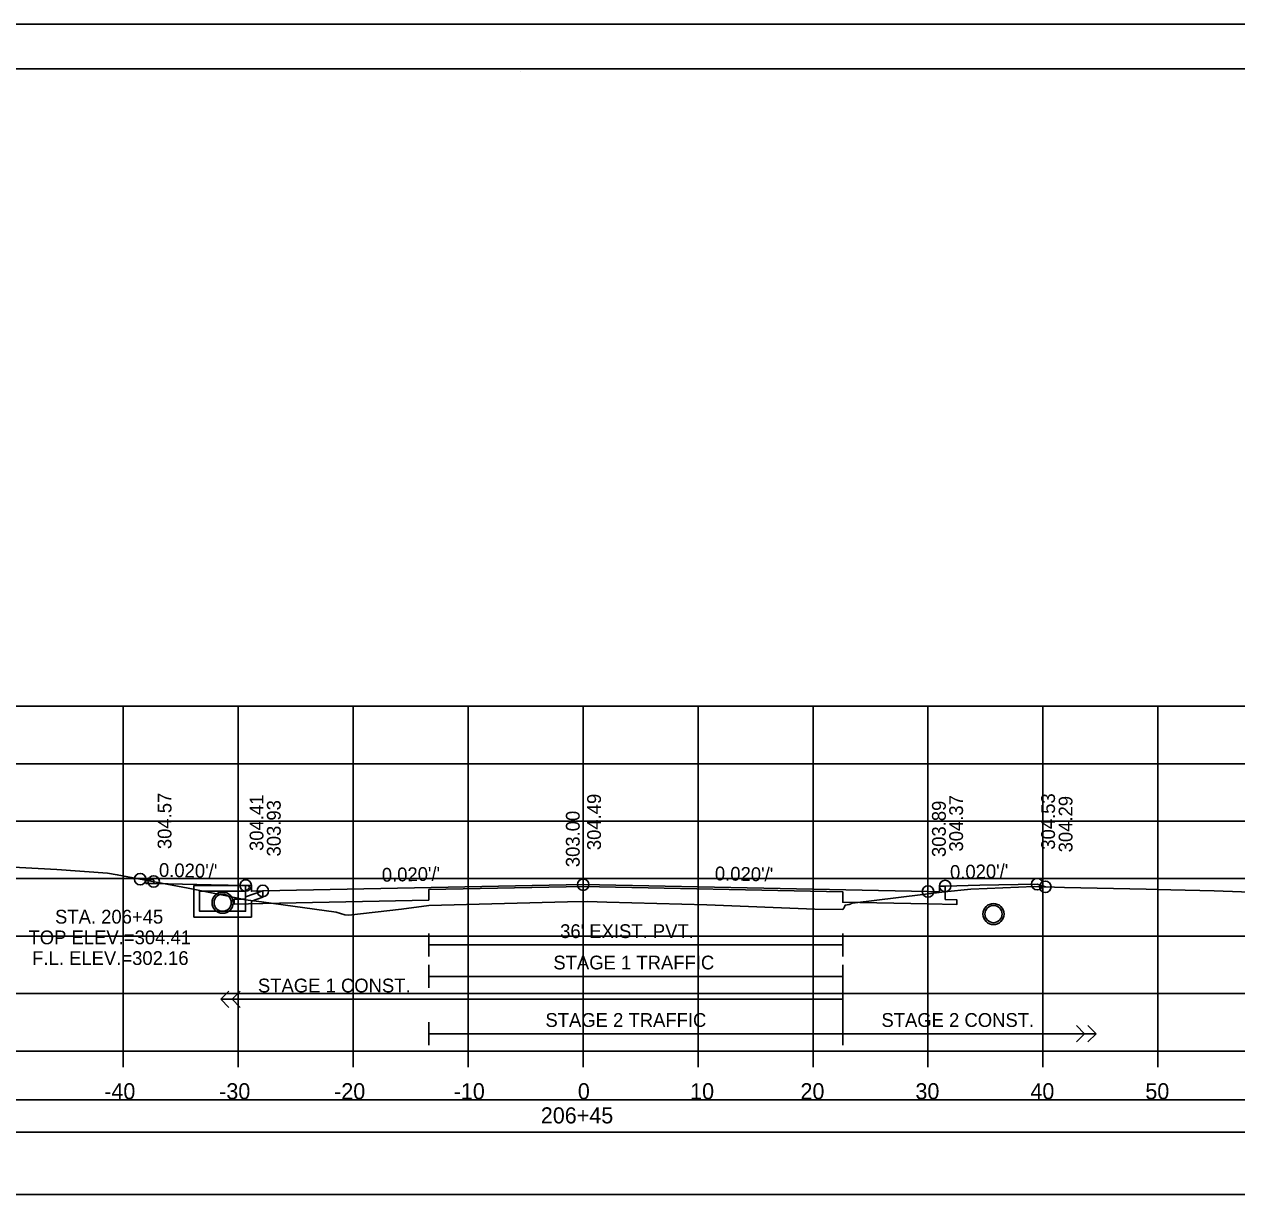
# Model space of a CAD drawing. Extents: x 1368122 to 1710785, y 373130 to 557566.
# Drawn here: x 1369973.6 to 1370079.1, y 374307.6 to 374410.4 of the extents above; entities that cross this region are included whole.
import ezdxf

# ---------------------------------------------------------------- set-up
doc = ezdxf.new("R2010")
doc.units = 0
for name, color, linetype in [('Default', 7, 'Continuous'), ('R_Alt Surface', 7, 'Continuous'), ('R_Axis', 7, 'Continuous'), ('R_Axis Annot', 7, 'Continuous'), ('R_Border', 7, 'Continuous'), ('R_Exist Surface', 7, 'Continuous'), ('R_Fin Surface', 7, 'Continuous'), ('R_Grid', 7, 'Continuous'), ('R_No Plot', 7, 'Continuous'), ('R_Striping', 7, 'Continuous'), ('R_Water', 7, 'Continuous'), ('R_Water Annot', 7, 'Continuous'), ('R_Xsect Elev', 7, 'Continuous'), ('R_Xsect Slope', 7, 'Continuous')]:
    doc.layers.add(name, color=color, linetype=linetype)

msp = doc.modelspace()

# ---------------------------------------------------------------- linework, layer by layer
for points in [[(1369873.09, 374313.94), (1370171.39, 374313.94), (1370171.39, 374316.75), (1369873.09, 374316.75)], [(1369873.09, 374308.52), (1370171.39, 374308.52), (1370171.39, 374313.94), (1369873.09, 374313.94)]]:
    msp.add_lwpolyline(points, close=True)
at = {"layer": 'Default'}
for p, q in [((1369984.27, 374335.92), (1369984.21, 374335.86)), ((1369984.81, 374335.94), (1369984.27, 374335.94)), ((1369984.27, 374335.94), (1369984.27, 374335.92)), ((1369984.81, 374335.92), (1369984.27, 374335.92)), ((1369984.81, 374335.92), (1369984.81, 374335.94)), ((1369984.88, 374335.86), (1369984.81, 374335.92)), ((1369984.88, 374335.57), (1369984.88, 374335.86))]:
    msp.add_line(p, q, dxfattribs=at)
msp.add_lwpolyline([(1369984.21, 374335.86), (1369984.21, 374335.58), (1369984.88, 374335.57)], dxfattribs=at)
at = {"layer": 'R_Alt Surface'}
for points in [[(1370053.74, 374335.36), (1370053.74, 374334.19), (1370054.74, 374334.17), (1370054.74, 374333.75), (1370052.24, 374333.8), (1370044.82, 374333.95), (1370044.82, 374334.86), (1370022.24, 374335.31), (1370008.81, 374335.05), (1370008.81, 374334.13), (1369994.38, 374333.84), (1369991.88, 374333.79), (1369991.88, 374334.21), (1369992.88, 374334.23), (1369992.88, 374335.41)], [(1370008.81, 374331.23), (1370008.81, 374329.23)], [(1370044.82, 374331.23), (1370044.82, 374329.23)], [(1370008.81, 374330.23), (1370044.82, 374330.23)]]:
    msp.add_lwpolyline(points, dxfattribs=at)
at = {"layer": 'R_Axis'}
for p, q in [((1369872.24, 374321), (1370172.24, 374321)), ((1369982.24, 374319.6), (1369982.24, 374321)), ((1369992.24, 374319.6), (1369992.24, 374321)), ((1370002.24, 374319.6), (1370002.24, 374321)), ((1370012.24, 374319.6), (1370012.24, 374321)), ((1370022.24, 374319.6), (1370022.24, 374321)), ((1370032.24, 374319.6), (1370032.24, 374321)), ((1370042.24, 374319.6), (1370042.24, 374321)), ((1370052.24, 374319.6), (1370052.24, 374321)), ((1370062.24, 374319.6), (1370062.24, 374321)), ((1370072.24, 374319.6), (1370072.24, 374321))]:
    msp.add_line(p, q, dxfattribs=at)
at = {"layer": 'R_Border'}
for p, q in [((1369864.24, 374406.46), (1370180.42, 374406.46)), ((1370016.76, 374406.2), (1370016.76, 374406.2)), ((1370016.76, 374406.2), (1370016.76, 374406.2))]:
    msp.add_line(p, q, dxfattribs=at)
at = {"layer": 'R_Exist Surface'}
msp.add_lwpolyline([(1369971.58, 374337.06), (1369976.46, 374336.8), (1369980.85, 374336.49), (1369981.71, 374336.34), (1369987.88, 374335.16), (1369991.37, 374334.48), (1369992.87, 374334.17), (1369994.25, 374333.97), (1370000.75, 374333.09), (1370001.5, 374332.86), (1370001.85, 374332.81), (1370006.43, 374333.35), (1370008.81, 374333.67), (1370020.87, 374333.97), (1370022.61, 374334.01), (1370024.31, 374333.96), (1370032.99, 374333.71), (1370042.4, 374333.35), (1370044.82, 374333.33), (1370044.93, 374333.44), (1370044.97, 374333.54), (1370045.03, 374333.69), (1370045.39, 374333.74), (1370045.55, 374333.82), (1370045.56, 374333.84), (1370045.67, 374333.86), (1370053.69, 374334.86), (1370055.97, 374335.1), (1370057.39, 374335.14), (1370061.48, 374335.31), (1370064.12, 374335.24), (1370071.23, 374335.08), (1370073.36, 374335.03), (1370077.14, 374334.95), (1370085.9, 374334.61)], dxfattribs=at)
at = {"layer": 'R_Fin Surface'}
msp.add_lwpolyline([(1369984.88, 374335.57), (1369989.88, 374335.47), (1369992.88, 374335.41), (1369993.38, 374335.41), (1369993.38, 374334.91), (1369994.38, 374334.93), (1370019.29, 374335.43), (1370022.24, 374335.48), (1370052.24, 374334.88), (1370053.24, 374334.86), (1370053.24, 374335.36), (1370053.74, 374335.36), (1370056.74, 374335.42), (1370061.74, 374335.52), (1370062.45, 374335.29)], dxfattribs=at)
at = {"layer": 'R_Grid'}
for p, q in [((1369872.24, 374351), (1370172.24, 374351)), ((1369982.24, 374321), (1369982.24, 374351)), ((1369992.24, 374321), (1369992.24, 374351)), ((1370002.24, 374321), (1370002.24, 374351)), ((1370012.24, 374321), (1370012.24, 374351)), ((1370022.24, 374321), (1370022.24, 374351)), ((1370032.24, 374321), (1370032.24, 374351)), ((1370042.24, 374321), (1370042.24, 374351)), ((1370052.24, 374321), (1370052.24, 374351)), ((1370062.24, 374321), (1370062.24, 374351)), ((1370072.24, 374321), (1370072.24, 374351)), ((1369872.24, 374346), (1370172.24, 374346)), ((1369872.24, 374341), (1370172.24, 374341)), ((1369872.24, 374336), (1370172.24, 374336)), ((1369872.24, 374331), (1370172.24, 374331)), ((1369872.24, 374326), (1370172.24, 374326)), ((1369872.24, 374321), (1370172.24, 374321))]:
    msp.add_line(p, q, dxfattribs=at)
at = {"layer": 'R_No Plot'}
msp.add_line((1369851.84, 374410.35), (1370185.17, 374410.35), dxfattribs=at)
for points in [[(1369851.83, 374410.35), (1370185.17, 374410.35), (1370185.17, 374197.02), (1369851.83, 374197.02)], [(1370098.16, 374406.46), (1370117.78, 374406.46), (1370117.78, 374396.58), (1370133.89, 374396.58), (1370157.09, 374396.58), (1370157.21, 374368.42), (1370180.42, 374368.42), (1370180.42, 374201), (1369864.24, 374201), (1369864.24, 374406.46)]]:
    msp.add_lwpolyline(points, close=True, dxfattribs=at)
for centre, radius in [((1369983.71, 374335.96), 0.5), ((1369984.88, 374335.76), 0.5), ((1369992.88, 374335.41), 0.5), ((1369994.38, 374334.93), 0.5), ((1370022.24, 374335.48), 0.5), ((1370052.24, 374334.88), 0.5), ((1370053.74, 374335.36), 0.5), ((1370061.74, 374335.52), 0.5), ((1370062.45, 374335.29), 0.5), ((1369990.88, 374333.91), 0.917), ((1370057.94, 374332.92), 0.917)]:
    msp.add_circle(centre, radius, dxfattribs=at)
at = {"layer": 'R_Striping'}
for p, q in [((1369990.71, 374325.5), (1369991.41, 374326.21)), ((1369991.71, 374325.5), (1369992.41, 374326.21)), ((1369991.41, 374324.79), (1369990.71, 374325.5)), ((1369992.41, 374324.79), (1369991.71, 374325.5)), ((1370065.87, 374322.5), (1370065.16, 374323.21)), ((1370066.87, 374322.5), (1370066.16, 374323.21)), ((1370066.87, 374322.5), (1370044.82, 374322.5)), ((1370065.16, 374321.79), (1370065.87, 374322.5)), ((1370066.16, 374321.79), (1370066.87, 374322.5))]:
    msp.add_line(p, q, dxfattribs=at)
for points in [[(1370008.81, 374328.5), (1370008.81, 374326.5)], [(1370044.82, 374328.5), (1370044.82, 374321.5)], [(1370008.81, 374327.5), (1370044.82, 374327.5)], [(1370044.82, 374325.5), (1369990.71, 374325.5)], [(1370008.81, 374323.5), (1370008.81, 374321.5)], [(1370008.81, 374322.5), (1370044.82, 374322.5)]]:
    msp.add_lwpolyline(points, dxfattribs=at)
at = {"layer": 'R_Water'}
for p, q in [((1369988.38, 374335.41), (1369993.13, 374335.41)), ((1369988.38, 374333.91), (1369988.38, 374335.41)), ((1369993.21, 374335.24), (1369993.13, 374335.41)), ((1369988.88, 374333.91), (1369988.88, 374334.91)), ((1369988.88, 374334.91), (1369992.88, 374334.91)), ((1369993.21, 374335.24), (1369992.88, 374334.91)), ((1369994.38, 374334.93), (1369992.88, 374334.41)), ((1369992.88, 374333.91), (1369992.88, 374334.41)), ((1369994.38, 374334.4), (1369993.38, 374334.05)), ((1369993.38, 374333.91), (1369993.38, 374334.05))]:
    msp.add_line(p, q, dxfattribs=at)
for points in [[(1369994.38, 374334.4), (1369994.38, 374334.93)], [(1369993.38, 374333.91), (1369993.38, 374332.66), (1369990.88, 374332.66), (1369988.38, 374332.66), (1369988.38, 374333.91)], [(1369992.88, 374333.91), (1369992.88, 374333.16), (1369990.88, 374333.16), (1369988.88, 374333.16), (1369988.88, 374333.91)]]:
    msp.add_lwpolyline(points, dxfattribs=at)
for centre in [(1369990.88, 374333.91), (1370057.94, 374332.92)]:
    msp.add_circle(centre, 0.75, dxfattribs=at)
at = {"layer": 'R_Xsect Elev'}
msp.add_line((1370022.24, 374334), (1370022.24, 374344), dxfattribs=at)

# ---------------------------------------------------------------- texts
at = {"layer": 'R_Axis Annot'}
for s, p in [('-40', (1369980.58, 374316.8)), ('-30', (1369990.58, 374316.8)), ('-20', (1370000.58, 374316.8)), ('-10', (1370010.98, 374316.8)), ('0', (1370021.78, 374316.8)), ('10', (1370031.55, 374316.8)), ('20', (1370041.15, 374316.8)), ('30', (1370051.15, 374316.8)), ('40', (1370061.15, 374316.8)), ('50', (1370071.15, 374316.8)), ('206+45', (1370018.56, 374314.7))]:
    msp.add_text(s, height=1.4, dxfattribs=at).set_placement(p)
at = {"layer": 'R_Striping'}
for s, p in [('STAGE 1 TRAFFIC', (1370019.65, 374328.1)), ('STAGE 1 CONST.', (1369993.95, 374326.1)), ('STAGE 2 TRAFFIC', (1370018.96, 374323.1)), ('STAGE 2 CONST.', (1370048.19, 374323.1))]:
    msp.add_text(s, height=1.2, dxfattribs=at).set_placement(p)
at = {"layer": 'R_Water'}
msp.add_text("36' EXIST. PVT.", height=1.2, dxfattribs=at).set_placement((1370020.24, 374330.83))
at = {"layer": 'R_Water Annot'}
for s, p in [('STA. 206+45', (1369976.3, 374332.09)), ('TOP ELEV.=304.41', (1369973.99, 374330.29)), ('F.L. ELEV.=302.16', (1369974.31, 374328.49))]:
    msp.add_text(s, height=1.2, dxfattribs=at).set_placement(p)
at = {"layer": 'R_Xsect Elev'}
for s, p in [('304.57', (1369986.43, 374338.57)), ('304.41', (1369994.43, 374338.41)), ('303.93', (1369995.93, 374337.93)), ('304.49', (1370023.79, 374338.48)), ('303.89', (1370053.79, 374337.88)), ('304.37', (1370055.29, 374338.36)), ('304.53', (1370063.29, 374338.52)), ('304.29', (1370064.81, 374338.29)), ('303.00', (1370021.94, 374337))]:
    msp.add_text(s, height=1.2, rotation=90, dxfattribs=at).set_placement(p)
at = {"layer": 'R_Xsect Slope'}
for rotation, p in [(358.8542, (1369985.33, 374336.16)), (1.1458, (1370004.74, 374335.73)), (358.8542, (1370033.69, 374335.86)), (1.1458, (1370054.17, 374335.97))]:
    msp.add_text("0.020'/'", height=1.2, rotation=rotation, dxfattribs=at).set_placement(p)

doc.saveas('drawing.dxf')
